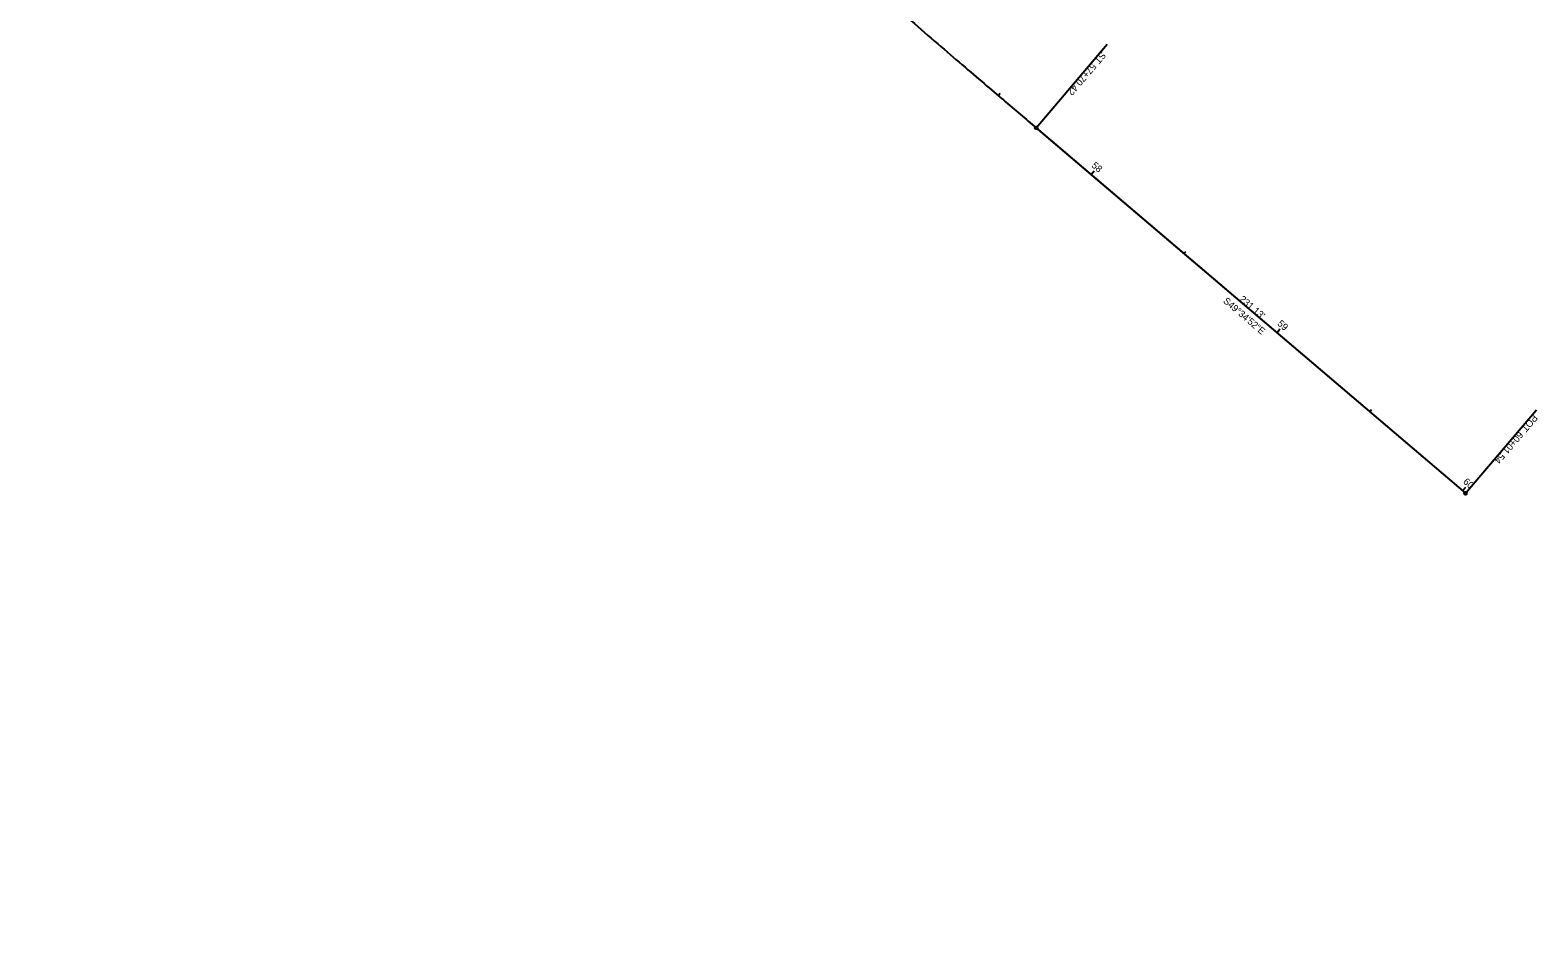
# Model space of a CAD drawing. Extents: x 1492452 to 1496782, y 514026 to 517659.
# Drawn here: x 1494344 to 1494962, y 514419 to 514788 of the extents above; entities that cross this region are included whole.
import ezdxf

# ---------------------------------------------------------------- set-up
doc = ezdxf.new("R2010")
doc.units = 0
for name, color, linetype in [('Default', 7, 'Continuous'), ('DT_X_Contour_Major', 7, 'Continuous'), ('DT_X_Contour_Minor', 7, 'Continuous'), ('DT_X_Contour_Text', 7, 'Continuous'), ('DT_X_Spot_Elev', 7, 'Continuous'), ('GE_X_Cells', 7, 'Continuous'), ('PV_X_Curb', 7, 'Continuous'), ('PV_X_EOP', 7, 'Continuous'), ('PV_X_Shoulder_Aggregate', 7, 'Continuous'), ('RD_X_GR_Bar', 7, 'Continuous'), ('RD_X_GR_Rt', 7, 'Continuous'), ('RD_X_Wall', 7, 'Continuous'), ('SV_X_Toe_of_Slope', 7, 'Continuous'), ('SV_X_Top_of_Bank', 7, 'Continuous'), ('XS_X_Ground_Line', 7, 'Continuous')]:
    doc.layers.add(name, color=color, linetype=linetype)

msp = doc.modelspace()

# ---------------------------------------------------------------- linework, layer by layer
at = {"layer": 'Default'}
msp.add_arc((1486425.91, 524780.42), 12277.67, 302.444021, 313.600151, dxfattribs=at)
at = {"layer": 'DT_X_Contour_Minor'}
msp.add_line((1494931.28, 514599.14), (1494932.57, 514600.67), dxfattribs=at)
at = {"layer": 'GE_X_Cells'}
msp.add_arc((1486425.91, 524780.42), 12277.67, 302.444021, 313.600151, dxfattribs=at)
at = {"layer": 'PV_X_EOP'}
for p, q in [((1494756.49, 514748), (1494785.66, 514782.26)), ((1494932.45, 514598.14), (1494961.63, 514632.4))]:
    msp.add_line(p, q, dxfattribs=at)
for centre in [(1494756.49, 514748), (1494932.45, 514598.14)]:
    msp.add_circle(centre, 0.6, dxfattribs=at)
at = {"layer": 'PV_X_Shoulder_Aggregate'}
for p, q in [((1494740.95, 514761.24), (1494741.73, 514762.15)), ((1494779.01, 514728.82), (1494780.31, 514730.34)), ((1494817.08, 514696.4), (1494817.86, 514697.31)), ((1494855.14, 514663.98), (1494856.44, 514665.5)), ((1494893.21, 514631.56), (1494893.99, 514632.48)), ((1494931.28, 514599.14), (1494932.57, 514600.67))]:
    msp.add_line(p, q, dxfattribs=at)
at = {"layer": 'RD_X_GR_Rt'}
for p, q in [((1494756.49, 514748), (1494785.66, 514782.26)), ((1494932.45, 514598.14), (1494961.63, 514632.4))]:
    msp.add_line(p, q, dxfattribs=at)
for centre in [(1494756.49, 514748), (1494932.45, 514598.14)]:
    msp.add_circle(centre, 0.6, dxfattribs=at)
at = {"layer": 'RD_X_Wall'}
for p, q in [((1494779.01, 514728.82), (1494779.79, 514729.73)), ((1494855.14, 514663.98), (1494855.92, 514664.89)), ((1494931.28, 514599.14), (1494932.57, 514600.67))]:
    msp.add_line(p, q, dxfattribs=at)
at = {"layer": 'SV_X_Top_of_Bank'}
for p in [(1494756.18, 514748.26), (1494756.49, 514748)]:
    msp.add_line(p, (1494932.45, 514598.14), dxfattribs=at)
msp.add_open_spline([(1494608.11, 514882), (1494612.01, 514878.04), (1494619.86, 514870.19), (1494635.79, 514854.68), (1494656.04, 514835.67), (1494680.78, 514813.33), (1494705.84, 514791.35), (1494726.9, 514773.23), (1494743.8, 514758.81), (1494752.26, 514751.6), (1494756.49, 514748)], degree=3, dxfattribs=at)
msp.add_open_spline([(1494608.11, 514882), (1494612.01, 514878.04), (1494619.86, 514870.19), (1494635.79, 514854.68), (1494656.04, 514835.67), (1494680.78, 514813.33), (1494705.84, 514791.35), (1494726.9, 514773.23), (1494743.8, 514758.81), (1494752.26, 514751.6), (1494756.49, 514748)], degree=3, dxfattribs=at)
at = {"layer": 'XS_X_Ground_Line'}
for p, q in [((1494756.49, 514748), (1494785.66, 514782.26)), ((1494932.45, 514598.14), (1494961.63, 514632.4))]:
    msp.add_line(p, q, dxfattribs=at)
for centre in [(1494756.49, 514748), (1494932.45, 514598.14)]:
    msp.add_circle(centre, 0.6, dxfattribs=at)

# ---------------------------------------------------------------- texts
at = {"layer": 'DT_X_Contour_Major'}
msp.add_text("231.13'", height=2.8, rotation=319.58116, dxfattribs=at).set_placement((1494839.56, 514677.31))
at = {"layer": 'DT_X_Contour_Minor'}
msp.add_text('60', height=2.8, rotation=319.58116, dxfattribs=at).set_placement((1494931.26, 514602.5))
at = {"layer": 'DT_X_Contour_Text'}
msp.add_text("231.13'", height=2.8, rotation=319.58116, dxfattribs=at).set_placement((1494839.56, 514677.31))
at = {"layer": 'DT_X_Spot_Elev'}
msp.add_text("231.13'", height=2.8, rotation=319.58116, dxfattribs=at).set_placement((1494839.56, 514677.31))
at = {"layer": 'PV_X_Curb'}
msp.add_text('S49°34\'52"E', height=2.8, rotation=319.58116, dxfattribs=at).set_placement((1494832.93, 514676.6))
at = {"layer": 'PV_X_EOP'}
for s, p in [('ST', (1494783.28, 514779.38)), ('57+70.42', (1494779.33, 514774.75)), ('POT', (1494960.2, 514630.66)), ('60+01.54', (1494954.28, 514623.71))]:
    msp.add_text(s, height=2.8, rotation=229.58116, dxfattribs=at).set_placement(p)
at = {"layer": 'PV_X_Shoulder_Aggregate'}
for s, p in [('58', (1494778.99, 514732.18)), ('59', (1494855.15, 514667.32)), ('60', (1494931.26, 514602.5))]:
    msp.add_text(s, height=2.8, rotation=319.58116, dxfattribs=at).set_placement(p)
at = {"layer": 'RD_X_GR_Bar'}
msp.add_text('S49°34\'52"E', height=2.8, rotation=319.58116, dxfattribs=at).set_placement((1494832.93, 514676.6))
at = {"layer": 'RD_X_GR_Rt'}
for s, p in [('ST', (1494783.28, 514779.38)), ('57+70.42', (1494779.33, 514774.75)), ('POT', (1494960.2, 514630.66)), ('60+01.54', (1494954.28, 514623.71))]:
    msp.add_text(s, height=2.8, rotation=229.58116, dxfattribs=at).set_placement(p)
at = {"layer": 'RD_X_Wall'}
msp.add_text('60', height=2.8, rotation=319.58116, dxfattribs=at).set_placement((1494931.26, 514602.5))
at = {"layer": 'SV_X_Toe_of_Slope'}
msp.add_text('S49°34\'52"E', height=2.8, rotation=319.58116, dxfattribs=at).set_placement((1494832.93, 514676.6))
at = {"layer": 'XS_X_Ground_Line'}
for s, p in [('ST', (1494783.28, 514779.38)), ('57+70.42', (1494779.33, 514774.75)), ('POT', (1494960.2, 514630.66)), ('60+01.54', (1494954.28, 514623.71))]:
    msp.add_text(s, height=2.8, rotation=229.58116, dxfattribs=at).set_placement(p)

doc.saveas('drawing.dxf')
